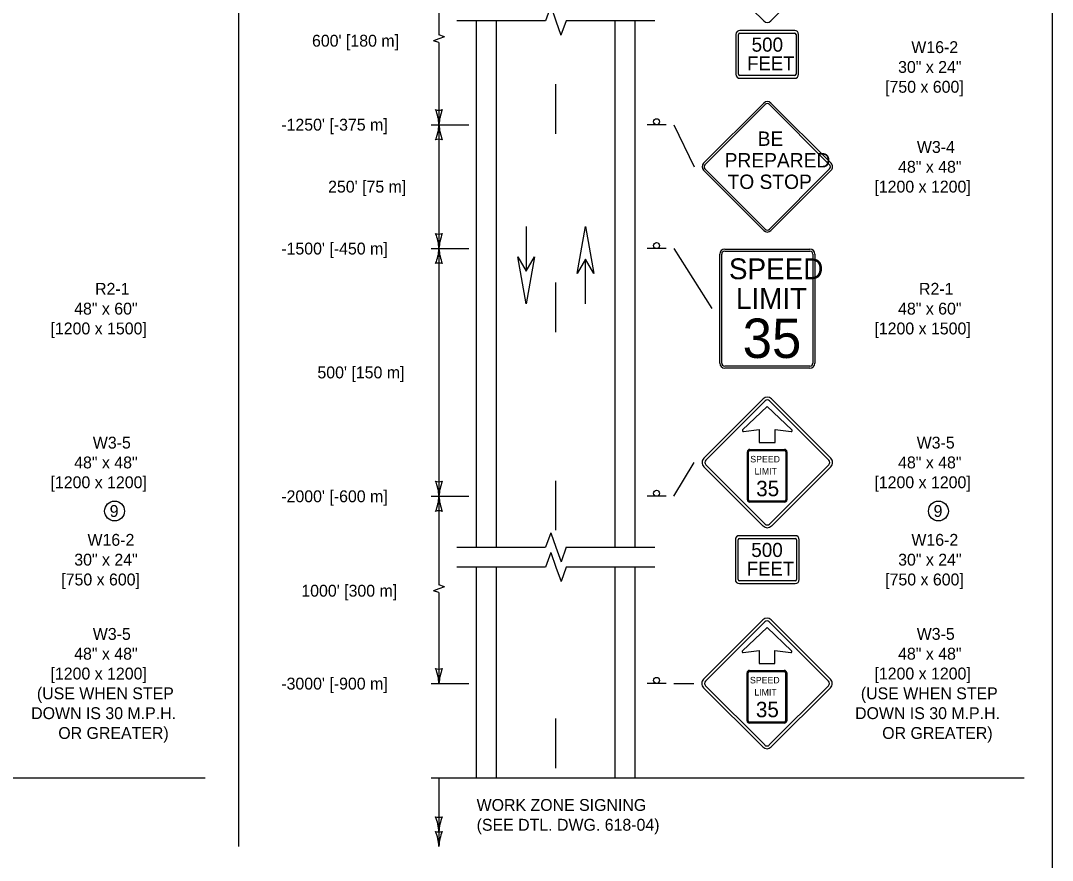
# Model space of a CAD drawing. Extents: x 49991.4 to 50021, y 49987.6 to 50011.4.
# Drawn here: x 50003.41 to 50008.61, y 50002.86 to 50007.09 of the extents above; entities that cross this region are included whole.
import ezdxf

# ---------------------------------------------------------------- set-up
doc = ezdxf.new("R2010")
doc.units = 0
for name, color, linetype in [('Level 1', 7, 'Continuous'), ('Level 2', 7, 'Continuous'), ('Level 3', 7, 'Continuous'), ('Level 6', 7, 'Continuous')]:
    doc.layers.add(name, color=color, linetype=linetype)

msp = doc.modelspace()

# ---------------------------------------------------------------- linework, layer by layer
at = {"layer": 'Level 1'}
for p, q in [((50006.8544, 50007.3966), (50007.1585, 50007.0926)), ((50007.1938, 50007.0926), (50007.4979, 50007.3966)), ((50005.7089, 50004.4375), (50005.7089, 50007.0935)), ((50005.8089, 50004.4375), (50005.8089, 50007.0935)), ((50006.4089, 50004.4375), (50006.4089, 50007.0935)), ((50006.5089, 50004.4375), (50006.5089, 50007.0935)), ((50007.018, 50007.0251), (50007.018, 50006.8235)), ((50007.0311, 50006.8235), (50007.0311, 50007.0251)), ((50007.3143, 50007.0453), (50007.0377, 50007.0453)), ((50007.0377, 50007.0318), (50007.3143, 50007.0318)), ((50007.3209, 50007.0251), (50007.3209, 50006.8235)), ((50007.3341, 50006.8235), (50007.3341, 50007.0251)), ((50007.3143, 50006.8168), (50007.0377, 50006.8168)), ((50006.1091, 50006.5231), (50006.1091, 50006.7731)), ((50007.0377, 50006.8033), (50007.3143, 50006.8033)), ((50007.1584, 50006.6787), (50006.8543, 50006.3747)), ((50007.1654, 50006.6717), (50006.8614, 50006.3676)), ((50007.4907, 50006.3676), (50007.1867, 50006.6717)), ((50007.4978, 50006.3747), (50007.1937, 50006.6787)), ((50006.6649, 50006.5694), (50006.5689, 50006.5694)), ((50006.8543, 50006.3393), (50007.1584, 50006.0353)), ((50006.8614, 50006.3464), (50007.1654, 50006.0423)), ((50007.1867, 50006.0423), (50007.4907, 50006.3464)), ((50007.1937, 50006.0353), (50007.4978, 50006.3393)), ((50005.9589, 50006.0559), (50005.9589, 50005.83)), ((50005.9593, 50006.0559), (50005.9593, 50005.83)), ((50006.6649, 50005.9444), (50006.5689, 50005.9444)), ((50006.961, 50005.9412), (50007.391, 50005.9412)), ((50006.961, 50005.9312), (50007.391, 50005.9312)), ((50006.2587, 50005.6657), (50006.2587, 50005.8916)), ((50006.2589, 50005.6657), (50006.2589, 50005.8916)), ((50006.936, 50005.3662), (50006.936, 50005.9162)), ((50006.946, 50005.3662), (50006.946, 50005.9162)), ((50007.406, 50005.9162), (50007.406, 50005.3662)), ((50007.416, 50005.9162), (50007.416, 50005.3662)), ((50006.1091, 50005.5231), (50006.1091, 50005.7731)), ((50007.391, 50005.3512), (50006.961, 50005.3512)), ((50007.391, 50005.3412), (50006.961, 50005.3412)), ((50007.1546, 50005.1858), (50006.8553, 50004.8865)), ((50007.1647, 50005.1757), (50006.8654, 50004.8764)), ((50007.176, 50005.1474), (50007.0516, 50005.0301)), ((50007.1546, 50005.1858), (50007.1546, 50005.1858)), ((50007.1647, 50005.1757), (50007.1647, 50005.1757)), ((50007.3004, 50005.0301), (50007.176, 50005.1474)), ((50007.4866, 50004.8764), (50007.1873, 50005.1757)), ((50007.4967, 50004.8865), (50007.1974, 50005.1858)), ((50007.0557, 50005.0214), (50007.1357, 50005.0314)), ((50007.1357, 50005.0314), (50007.1357, 50004.9659)), ((50007.2163, 50004.9659), (50007.2163, 50005.0314)), ((50007.2163, 50005.0314), (50007.2964, 50005.0214)), ((50007.1357, 50004.9659), (50007.2163, 50004.9659)), ((50007.0757, 50004.6771), (50007.0757, 50004.9184)), ((50007.0809, 50004.6771), (50007.0809, 50004.9184)), ((50007.0881, 50004.9309), (50007.2629, 50004.9309)), ((50007.0881, 50004.9257), (50007.2629, 50004.9257)), ((50007.1755, 50004.9309), (50007.1755, 50004.9309)), ((50007.2702, 50004.9184), (50007.2702, 50004.6771)), ((50007.2754, 50004.9184), (50007.2754, 50004.6771)), ((50006.8553, 50004.8437), (50007.1546, 50004.5444)), ((50006.8654, 50004.8538), (50007.1647, 50004.5545)), ((50007.1873, 50004.5545), (50007.4866, 50004.8538)), ((50007.1974, 50004.5444), (50007.4967, 50004.8437)), ((50006.1091, 50004.5231), (50006.1091, 50004.7731)), ((50006.6649, 50004.6944), (50006.5689, 50004.6944)), ((50007.2629, 50004.6698), (50007.0881, 50004.6698)), ((50007.2629, 50004.6646), (50007.0881, 50004.6646)), ((50007.0147, 50004.4754), (50007.0147, 50004.2738)), ((50007.0282, 50004.2738), (50007.0282, 50004.4754)), ((50007.3171, 50004.4956), (50007.0349, 50004.4956)), ((50007.0349, 50004.4821), (50007.3171, 50004.4821)), ((50007.3239, 50004.4754), (50007.3239, 50004.2738)), ((50007.3373, 50004.2738), (50007.3373, 50004.4754)), ((50005.7089, 50003.2739), (50005.7089, 50004.3375)), ((50005.8089, 50003.2739), (50005.8089, 50004.3375)), ((50006.4089, 50003.2739), (50006.4089, 50004.3375)), ((50006.5089, 50003.2739), (50006.5089, 50004.3375)), ((50007.3171, 50004.2671), (50007.0349, 50004.2671)), ((50007.0349, 50004.2537), (50007.3171, 50004.2537)), ((50007.1531, 50004.0707), (50006.8538, 50003.7714)), ((50007.1632, 50004.0606), (50006.8639, 50003.7613)), ((50007.1531, 50004.0707), (50007.1531, 50004.0707)), ((50007.1632, 50004.0606), (50007.1632, 50004.0606)), ((50007.4851, 50003.7613), (50007.1858, 50004.0606)), ((50007.4952, 50003.7714), (50007.1959, 50004.0707)), ((50007.1745, 50004.0323), (50007.0501, 50003.915)), ((50007.2989, 50003.915), (50007.1745, 50004.0323)), ((50007.0541, 50003.9063), (50007.1342, 50003.9164)), ((50007.1342, 50003.9164), (50007.1342, 50003.8508)), ((50007.2148, 50003.8508), (50007.2148, 50003.9164)), ((50007.2148, 50003.9164), (50007.2948, 50003.9063)), ((50007.1342, 50003.8508), (50007.2148, 50003.8508)), ((50007.0741, 50003.562), (50007.0741, 50003.8033)), ((50007.0793, 50003.562), (50007.0793, 50003.8033)), ((50007.0866, 50003.8158), (50007.2613, 50003.8158)), ((50007.0866, 50003.8106), (50007.2613, 50003.8106)), ((50007.174, 50003.8158), (50007.174, 50003.8158)), ((50007.2686, 50003.8033), (50007.2686, 50003.562)), ((50007.2738, 50003.8033), (50007.2738, 50003.562)), ((50006.6649, 50003.75), (50006.5689, 50003.75)), ((50006.8639, 50003.7388), (50007.1632, 50003.4395)), ((50007.1858, 50003.4395), (50007.4851, 50003.7388)), ((50006.8538, 50003.7287), (50007.1531, 50003.4294)), ((50007.1959, 50003.4294), (50007.4952, 50003.7287)), ((50006.1091, 50003.3226), (50006.1091, 50003.5726)), ((50007.2613, 50003.5547), (50007.0866, 50003.5547)), ((50007.2613, 50003.5495), (50007.0866, 50003.5495))]:
    msp.add_line(p, q, dxfattribs=at)
for points in [[(50008.6146, 50011.2628), (50000.3356, 50011.2628), (50000.3356, 50000.0624), (50008.6146, 50000.0624)], [(50006.2169, 50005.8193), (50006.2587, 50006.0558), (50006.3005, 50005.8193), (50006.2587, 50005.8915)], [(50006.0009, 50005.9023), (50005.9593, 50005.6658), (50005.9173, 50005.9023), (50005.9593, 50005.8301)]]:
    msp.add_lwpolyline(points, close=True, dxfattribs=at)
for centre in [(50006.6169, 50006.5845), (50006.6169, 50005.9595), (50006.6169, 50004.7095), (50006.6169, 50003.7652)]:
    msp.add_circle(centre, 0.0152, dxfattribs=at)
for centre, radius, start, end in [((50007.176, 50007.1103), 0.025, 225, 314.9996), ((50007.176, 50006.6609), 0.025, 45, 135), ((50007.176, 50006.6609), 0.015, 45, 135), ((50006.872, 50006.3569), 0.025, 135, 225), ((50006.872, 50006.3569), 0.015, 135, 225), ((50007.4801, 50006.3569), 0.015, 315, 45.0002), ((50007.4801, 50006.3569), 0.025, 315, 45.0002), ((50007.176, 50006.0528), 0.025, 225, 314.9996), ((50007.176, 50006.0528), 0.015, 225, 314.9996), ((50006.9611, 50005.9162), 0.025, 90, 180), ((50006.9611, 50005.9162), 0.015, 90, 180), ((50007.3911, 50005.9162), 0.025, 0, 90), ((50007.3911, 50005.9162), 0.015, 0, 90), ((50006.9611, 50005.3662), 0.025, 180, 270), ((50006.9611, 50005.3662), 0.015, 180, 270), ((50007.3911, 50005.3662), 0.025, 270, 0), ((50007.3911, 50005.3662), 0.015, 270, 0), ((50007.176, 50005.1644), 0.0302, 45.0001, 134.9999), ((50007.176, 50005.1644), 0.016, 45.0001, 134.9999), ((50007.0552, 50005.0265), 0.00508, 134.6287, 275.8295), ((50007.2969, 50005.0265), 0.00509, 264.3826, 45.1649), ((50006.8767, 50004.8651), 0.0302, 134.9999, 225.0001), ((50007.0881, 50004.9184), 0.0125, 90, 180), ((50007.0881, 50004.9184), 0.00728, 90, 180), ((50007.2629, 50004.9184), 0.0125, 360, 90), ((50007.2629, 50004.9184), 0.00728, 360, 90), ((50007.4753, 50004.8651), 0.0302, 314.9999, 45.0001), ((50006.8767, 50004.8651), 0.016, 134.9999, 225.0001), ((50007.4753, 50004.8651), 0.016, 314.9999, 45.0001), ((50007.0881, 50004.6771), 0.0125, 180, 270), ((50007.0881, 50004.6771), 0.00728, 180, 270), ((50007.2629, 50004.6771), 0.00728, 270, 360), ((50007.2629, 50004.6771), 0.0125, 270, 360), ((50007.176, 50004.5658), 0.0302, 225.0001, 314.9999), ((50007.176, 50004.5658), 0.016, 225.0001, 314.9999), ((50007.0349, 50004.4754), 0.0202, 90, 180), ((50007.0349, 50004.4754), 0.00672, 90, 180), ((50007.3171, 50004.4754), 0.0202, 0, 90), ((50007.3171, 50004.4754), 0.00672, 0, 90), ((50007.0349, 50004.2738), 0.0202, 180, 270), ((50007.0349, 50004.2738), 0.00672, 180, 270), ((50007.3171, 50004.2738), 0.00672, 270, 360), ((50007.3171, 50004.2738), 0.0202, 270, 360), ((50007.1745, 50004.0493), 0.0302, 45.0001, 134.9999), ((50007.1745, 50004.0493), 0.016, 45.0001, 134.9999), ((50007.0536, 50003.9114), 0.00508, 134.6287, 275.8295), ((50007.2953, 50003.9114), 0.00509, 264.3826, 45.1649), ((50007.0866, 50003.8033), 0.0125, 90, 180), ((50007.0866, 50003.8033), 0.00728, 90, 180), ((50007.2613, 50003.8033), 0.0125, 360, 90), ((50007.2613, 50003.8033), 0.00728, 360, 90), ((50006.8752, 50003.75), 0.0302, 134.9999, 225.0001), ((50006.8752, 50003.75), 0.016, 134.9999, 225.0001), ((50007.4738, 50003.75), 0.016, 314.9999, 45.0001), ((50007.4738, 50003.75), 0.0302, 314.9999, 45.0001), ((50007.0866, 50003.562), 0.0125, 180, 270), ((50007.0866, 50003.562), 0.00728, 180, 270), ((50007.2613, 50003.562), 0.00728, 270, 360), ((50007.2613, 50003.562), 0.0125, 270, 360), ((50007.1745, 50003.4507), 0.0302, 225.0001, 314.9999), ((50007.1745, 50003.4507), 0.016, 225.0001, 314.9999)]:
    msp.add_arc(centre, radius, start, end, dxfattribs=at)
for centre, major_axis, start_param, end_param in [((50007.0377, 50007.0251), (0, 0.0202), 0, 1.570796), ((50007.0377, 50007.0251), (0, 0.00672), 0, 1.570796), ((50007.3143, 50007.0251), (0, 0.0202), 4.712389, 6.283185), ((50007.3143, 50007.0251), (0, 0.00672), 4.712389, 6.283185), ((50007.0377, 50006.8235), (0, -0.0202), 4.712389, 6.283185), ((50007.0377, 50006.8235), (0, -0.00672), 4.712389, 6.283185), ((50007.3143, 50006.8235), (0, -0.00672), 0, 1.570796), ((50007.3143, 50006.8235), (0, -0.0202), 0, 1.570796)]:
    msp.add_ellipse(centre, major_axis=major_axis, ratio=0.98, start_param=start_param, end_param=end_param, dxfattribs=at)
at = {"layer": 'Level 2'}
for centre in [(50003.8818, 50004.6201), (50008.0396, 50004.6201)]:
    msp.add_circle(centre, 0.05, dxfattribs=at)
at = {"layer": 'Level 3'}
for p, q in [((50004.5077, 50011.2418), (50004.5077, 50002.9277)), ((50005.5191, 50007.5052), (50005.5191, 50007.0221)), ((50005.5465, 50007.0124), (50005.5191, 50007.0221)), ((50005.5191, 50007.0027), (50005.4917, 50006.993)), ((50005.5191, 50006.9833), (50005.4917, 50006.993)), ((50005.5465, 50007.0124), (50005.5191, 50007.0027)), ((50005.5191, 50006.9833), (50005.5191, 50006.5693)), ((50005.479, 50006.5693), (50005.6689, 50006.5693)), ((50005.5191, 50006.5693), (50005.5191, 50005.9443)), ((50006.7049, 50006.5694), (50006.807, 50006.3569)), ((50005.479, 50005.9443), (50005.6689, 50005.9443)), ((50005.5191, 50005.9443), (50005.5191, 50004.6943)), ((50006.7049, 50005.9444), (50006.896, 50005.6412)), ((50006.7049, 50004.6944), (50006.8065, 50004.8651)), ((50005.479, 50004.6943), (50005.6689, 50004.6943)), ((50005.5191, 50004.6943), (50005.5191, 50004.2469)), ((50005.5191, 50004.2275), (50005.4917, 50004.2178)), ((50005.5191, 50004.2081), (50005.4917, 50004.2178)), ((50005.5191, 50004.2081), (50005.519, 50003.7492)), ((50005.5465, 50004.2372), (50005.5191, 50004.2469)), ((50005.5465, 50004.2372), (50005.5191, 50004.2275)), ((50005.479, 50003.7492), (50005.6689, 50003.7492)), ((50006.7049, 50003.75), (50006.8049, 50003.75)), ((50001.3453, 50003.2739), (50004.3393, 50003.2739)), ((50005.479, 50003.2739), (50008.4725, 50003.2739)), ((50005.5191, 50003.2739), (50005.5191, 50002.9277))]:
    msp.add_line(p, q, dxfattribs=at)
for centre, radius, start, end in [((50005.2969, 50006.5602), 0.2223, 2.3605, 22.544), ((50005.5191, 50006.6975), 0.0548, 252.1388, 287.8612), ((50005.7518, 50006.5578), 0.233, 157.9228, 177.1727), ((50005.2969, 50006.5785), 0.2223, 337.456, 357.6395), ((50005.7518, 50006.5808), 0.233, 182.8273, 202.0772), ((50005.5191, 50006.4411), 0.0548, 72.1388, 107.8612), ((50005.2969, 50005.9352), 0.2223, 2.3605, 22.544), ((50005.5191, 50006.0725), 0.0548, 252.1388, 287.8612), ((50005.7518, 50005.9328), 0.233, 157.9228, 177.1727), ((50005.2969, 50005.9535), 0.2223, 337.456, 357.6395), ((50005.7518, 50005.9558), 0.233, 182.8273, 202.0772), ((50005.5191, 50005.8161), 0.0548, 72.1388, 107.8612), ((50005.2969, 50004.6852), 0.2223, 2.3605, 22.544), ((50005.5191, 50004.8225), 0.0548, 252.1388, 287.8612), ((50005.7518, 50004.6828), 0.233, 157.9228, 177.1727), ((50005.2969, 50004.7035), 0.2223, 337.456, 357.6395), ((50005.7518, 50004.7058), 0.233, 182.8273, 202.0772), ((50005.5191, 50004.5661), 0.0548, 72.1388, 107.8612), ((50005.2969, 50003.74), 0.2223, 2.3605, 22.544), ((50005.519, 50003.8774), 0.0548, 252.1388, 287.8612), ((50005.7518, 50003.7377), 0.233, 157.9228, 177.1727), ((50005.5191, 50003.1293), 0.0548, 252.1388, 287.8612), ((50005.2863, 50002.9896), 0.233, 2.8273, 22.0772), ((50005.7412, 50002.9919), 0.2223, 157.456, 177.6395), ((50005.5191, 50003.0559), 0.0548, 252.1388, 287.8612), ((50005.2863, 50002.9162), 0.233, 2.8273, 22.0772), ((50005.7412, 50002.9185), 0.2223, 157.456, 177.6395)]:
    msp.add_arc(centre, radius, start, end, dxfattribs=at)
at = {"layer": 'Level 6'}
for p, q in [((50006.083, 50007.1666), (50006.0571, 50007.0935)), ((50006.083, 50007.1666), (50006.1089, 50007.0935)), ((50006.0571, 50007.0935), (50005.6089, 50007.0935)), ((50006.1089, 50007.0935), (50006.1348, 50007.0204)), ((50006.1607, 50007.0935), (50006.1348, 50007.0204)), ((50006.6089, 50007.0935), (50006.1607, 50007.0935)), ((50006.0832, 50004.5106), (50006.0572, 50004.4375)), ((50006.0832, 50004.5106), (50006.109, 50004.4375)), ((50005.609, 50004.4375), (50006.0572, 50004.4375)), ((50006.0832, 50004.4106), (50006.0572, 50004.3375)), ((50006.0832, 50004.4106), (50006.109, 50004.3375)), ((50006.109, 50004.4375), (50006.135, 50004.3644)), ((50006.1608, 50004.4375), (50006.135, 50004.3644)), ((50006.1608, 50004.4375), (50006.609, 50004.4375)), ((50006.0572, 50004.3375), (50005.609, 50004.3375)), ((50006.109, 50004.3375), (50006.135, 50004.2644)), ((50006.1608, 50004.3375), (50006.135, 50004.2644)), ((50006.609, 50004.3375), (50006.1608, 50004.3375))]:
    msp.add_line(p, q, dxfattribs=at)

# ---------------------------------------------------------------- texts
at = {"layer": 'Level 1'}
for s, height, p in [('500', 0.07124, (50007.0967, 50006.9377)), ('FEET', 0.06989, (50007.0748, 50006.8436)), ('BE', 0.0725, (50007.1275, 50006.4625)), ('PREPARED', 0.0725, (50006.9606, 50006.3537)), ('TO STOP', 0.0725, (50006.9753, 50006.245)), ('SPEED', 0.10512, (50006.9823, 50005.7897)), ('LIMIT', 0.10512, (50007.0177, 50005.6396)), ('35', 0.1989, (50007.0517, 50005.3923)), ('500', 0.07124, (50007.0951, 50004.3881)), ('FEET', 0.06989, (50007.0728, 50004.294))]:
    msp.add_text(s, height=height, dxfattribs=at).set_placement(p)
for s, height, p in [('SPEED', 0.03301, (50007.0902, 50004.8652)), ('LIMIT', 0.03301, (50007.112, 50004.8041)), ('35', 0.07775, (50007.12, 50004.6947)), ('SPEED', 0.03301, (50007.0886, 50003.7501)), ('LIMIT', 0.03301, (50007.1105, 50003.6891)), ('35', 0.07775, (50007.1185, 50003.5796))]:
    msp.add_text(s, height=height, rotation=360, dxfattribs=at).set_placement(p)
at = {"layer": 'Level 2'}
for s, height, p in [("600' [180 m]", 0.06, (50004.8783, 50006.963)), ('W16-2', 0.06, (50007.9029, 50006.9306)), ('30" x 24"', 0.06, (50007.836, 50006.8306)), ('[750 x 600]', 0.06, (50007.7704, 50006.7306)), ("-1250' [-375 m]", 0.06, (50004.7232, 50006.5393)), ('W3-4', 0.06, (50007.931, 50006.4269)), ('48" x 48"', 0.06, (50007.836, 50006.3269)), ("250' [75 m]", 0.06, (50004.9596, 50006.2268)), ('[1200 x 1200]', 0.06, (50007.7165, 50006.2269)), ("-1500' [-450 m]", 0.06, (50004.7232, 50005.9143)), ('R2-1', 0.06, (50003.7835, 50005.7112)), ('R2-1', 0.06, (50007.9415, 50005.7112)), ('48" x 60"', 0.06, (50003.678, 50005.6112)), ('48" x 60"', 0.06, (50007.836, 50005.6112)), ('[1200 x 1500]', 0.06, (50003.5585, 50005.5112)), ('[1200 x 1500]', 0.06, (50007.7165, 50005.5112)), ("500' [150 m]", 0.06, (50004.9057, 50005.2893)), ('W3-5', 0.05999, (50003.7722, 50004.9351)), ('W3-5', 0.05999, (50007.93, 50004.9351)), ('48" x 48"', 0.05999, (50003.6782, 50004.8351)), ('48" x 48"', 0.05999, (50007.836, 50004.8351)), ('[1200 x 1200]', 0.059993, (50003.5587, 50004.7351)), ('[1200 x 1200]', 0.059993, (50007.7165, 50004.7351)), ("-2000' [-600 m]", 0.06, (50004.7232, 50004.6643)), ('9', 0.06, (50003.8573, 50004.5901)), ('9', 0.06, (50008.0152, 50004.5901)), ('W16-2', 0.05999, (50003.7454, 50004.4446)), ('W16-2', 0.05999, (50007.9032, 50004.4446)), ('30" x 24"', 0.05999, (50003.6786, 50004.3446)), ('30" x 24"', 0.05999, (50007.8364, 50004.3446)), ('[750 x 600]', 0.059993, (50003.613, 50004.2446)), ('[750 x 600]', 0.059993, (50007.7708, 50004.2447)), ("1000' [300 m]", 0.06, (50004.8244, 50004.1878)), ('W3-5', 0.06, (50003.7721, 50003.9699)), ('W3-5', 0.06, (50007.9302, 50003.97)), ('48" x 48"', 0.06, (50003.6781, 50003.8699)), ('48" x 48"', 0.06, (50007.8361, 50003.87)), ('[1200 x 1200]', 0.06, (50003.5586, 50003.7699)), ('[1200 x 1200]', 0.06, (50007.7167, 50003.77)), ("-3000' [-900 m]", 0.06, (50004.7232, 50003.7192)), ('(USE WHEN STEP', 0.06, (50003.4899, 50003.67)), ('(USE WHEN STEP', 0.06, (50007.648, 50003.67)), ('DOWN IS 30 M.P.H.', 0.06, (50003.461, 50003.57)), ('DOWN IS 30 M.P.H.', 0.06, (50007.619, 50003.57)), ('OR GREATER)', 0.06, (50003.5979, 50003.47)), ('OR GREATER)', 0.06, (50007.7559, 50003.47)), ('WORK ZONE SIGNING', 0.06, (50005.7091, 50003.1069)), ('(SEE DTL. DWG. 618-04)', 0.06, (50005.7091, 50003.0069))]:
    msp.add_text(s, height=height, dxfattribs=at).set_placement(p)

doc.saveas('drawing.dxf')
